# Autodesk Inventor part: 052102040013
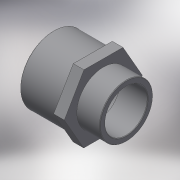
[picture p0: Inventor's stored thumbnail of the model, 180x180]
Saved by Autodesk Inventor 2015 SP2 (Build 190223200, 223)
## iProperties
Created: 2017-10
Part Number: 052102040013
Material: Generic
Description: PLASSON SOCKET NIPPLE THR-CE 50(40)-1.1/4"
Document SubType Name: Modeling
Designer: KIM
Density: 1 g/cm^3
Appearance: Default
Author: KIM
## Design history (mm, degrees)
derived "052102.ipt"
feature "Solid1::052102.ipt"
tag "TaggingFeature1"
body "Solid1"
other parameters: "d13" = 0, "d14" = 0.4, "d17" = 31, "d18" = 26.4, "d21" = 41.91, "d22" = 26, "d23" = 38, "d24" = 33.528, "d25" = 22, "d26" = -31, "R_" = 41.91, "B_" = 12, "L_" = 31, "lt_" = 22, "l_" = 26
